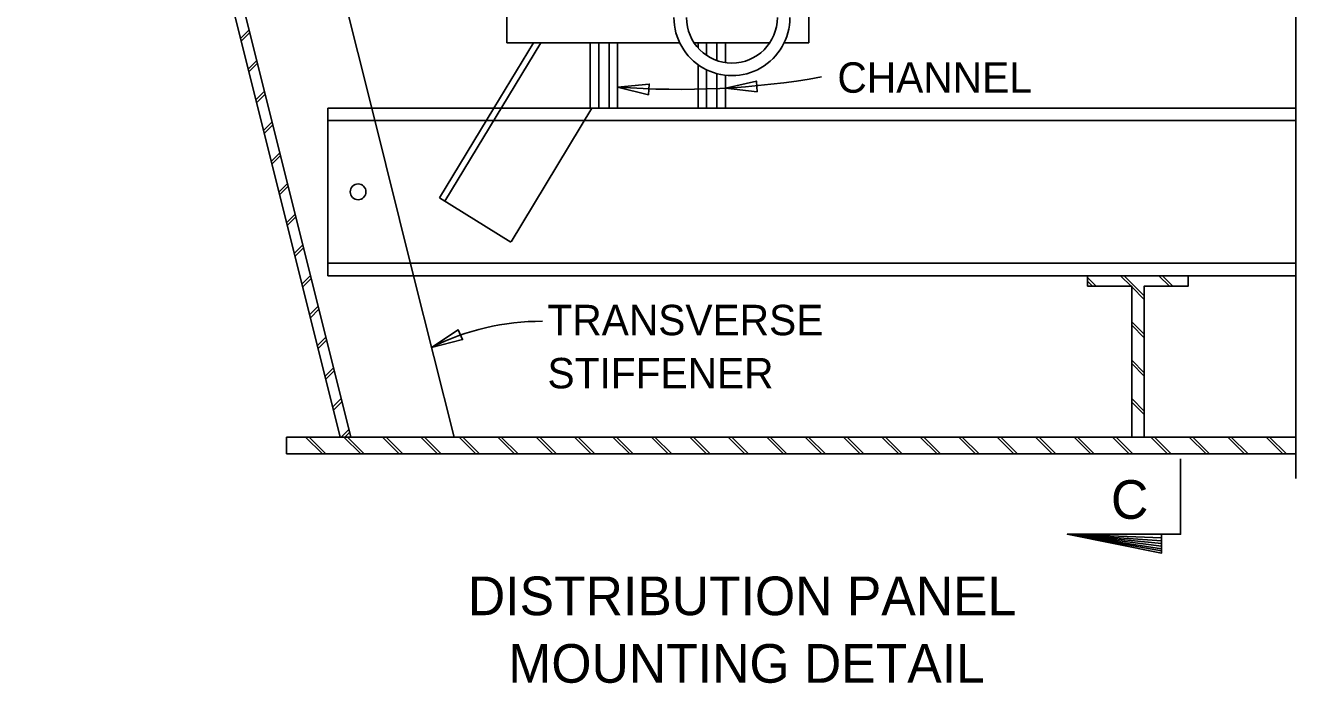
# Model space of a CAD drawing. Extents: x 927736.2 to 927809.6, y 636703.6 to 636757.7.
# Drawn here: x 927758.43 to 927774.19, y 636735.27 to 636743.33 of the extents above; entities that cross this region are included whole.
import ezdxf

# ---------------------------------------------------------------- set-up
doc = ezdxf.new("R2010")
doc.units = 0
for name, color, linetype in [('Default', 7, 'Continuous'), ('DimLines_dp', 7, 'Continuous'), ('Miscellaneous1', 7, 'Continuous'), ('Miscellaneous3', 7, 'Continuous')]:
    doc.layers.add(name, color=color, linetype=linetype)

msp = doc.modelspace()

# ---------------------------------------------------------------- linework, layer by layer
at = {"layer": 'DimLines_dp'}
for p, q in [((927772.357, 636737.056), (927771.201, 636737.099)), ((927771.201, 636737.099), (927772.357, 636737.019)), ((927772.357, 636736.985), (927771.201, 636737.099)), ((927771.201, 636737.099), (927772.357, 636736.951)), ((927772.357, 636736.92), (927771.201, 636737.099)), ((927771.201, 636737.099), (927772.357, 636736.895))]:
    msp.add_line(p, q, dxfattribs=at)
for points in [[(927774, 636737.782), (927774, 636747.055), (927773.809, 636747.055), (927774, 636747.139), (927774.191, 636747.222), (927774, 636747.222), (927774, 636756.677)], [(927772.589, 636738.024), (927772.589, 636737.099), (927771.201, 636737.099), (927772.357, 636736.867), (927772.357, 636737.099)]]:
    msp.add_lwpolyline(points, dxfattribs=at)
for points in [[(927765.688, 636742.581), (927766.067, 636742.487), (927766.077, 636742.617)], [(927767.01, 636742.568), (927767.398, 636742.524), (927767.391, 636742.654)], [(927763.409, 636739.389), (927763.788, 636739.484), (927763.736, 636739.603)]]:
    msp.add_lwpolyline(points, close=True, dxfattribs=at)
msp.add_arc((927766.454, 636752.53), 9.978, 265.6012, 280.0186, dxfattribs=at)
msp.add_ellipse((927764.747, 636736.471), major_axis=(-0.021, -3.238), ratio=0.953713, start_param=3.141601, end_param=3.59647, dxfattribs=at)
at = {"layer": 'Miscellaneous1'}
for p, q in [((927765.354, 636743.124), (927765.354, 636742.324)), ((927765.457, 636743.124), (927765.457, 636742.324)), ((927765.586, 636743.124), (927765.586, 636742.324)), ((927765.688, 636743.124), (927765.688, 636742.324)), ((927766.676, 636743.124), (927766.676, 636743.06)), ((927766.778, 636743.124), (927766.778, 636742.971)), ((927766.907, 636743.124), (927766.907, 636742.906)), ((927767.01, 636743.124), (927767.01, 636742.881)), ((927766.676, 636742.854), (927766.676, 636742.324)), ((927766.778, 636742.793), (927766.778, 636742.324)), ((927766.907, 636742.745), (927766.907, 636742.324)), ((927767.01, 636742.726), (927767.01, 636742.324))]:
    msp.add_line(p, q, dxfattribs=at)
for radius, start, end in [(0.711, 179.9955, 0.0001), (0.557, 180, 0)]:
    msp.add_arc((927767.09, 636743.432), radius, start, end, dxfattribs=at)
at = {"layer": 'Miscellaneous3'}
for p, q in [((927758.434, 636753.706), (927762.288, 636738.29)), ((927758.566, 636753.706), (927762.42, 636738.29)), ((927760.241, 636752.062), (927762.676, 636742.324)), ((927761.066, 636743.177), (927761.172, 636743.283)), ((927761.075, 636743.142), (927761.181, 636743.248)), ((927763.572, 636741.181), (927764.747, 636743.124)), ((927764.173, 636742.324), (927764.657, 636743.124)), ((927761.16, 636742.801), (927761.266, 636742.907)), ((927761.169, 636742.766), (927761.275, 636742.872)), ((927761.254, 636742.424), (927761.36, 636742.53)), ((927761.263, 636742.389), (927761.369, 636742.495)), ((927762.138, 636740.268), (927762.138, 636742.324)), ((927762.138, 636742.323), (927774, 636742.323)), ((927762.675, 636742.324), (927763.189, 636740.268)), ((927763.506, 636741.222), (927764.173, 636742.324)), ((927764.383, 636740.685), (927765.374, 636742.324)), ((927761.349, 636742.047), (927761.455, 636742.153)), ((927761.357, 636742.012), (927761.463, 636742.118)), ((927762.138, 636742.17), (927774, 636742.17)), ((927761.443, 636741.67), (927761.549, 636741.776)), ((927761.452, 636741.635), (927761.558, 636741.741)), ((927761.537, 636741.294), (927761.643, 636741.4)), ((927761.546, 636741.259), (927761.652, 636741.365)), ((927763.506, 636741.222), (927764.379, 636740.679)), ((927761.631, 636740.917), (927761.737, 636741.023)), ((927761.64, 636740.882), (927761.746, 636740.988)), ((927761.725, 636740.54), (927761.831, 636740.646)), ((927761.734, 636740.505), (927761.84, 636740.611)), ((927762.138, 636740.422), (927774, 636740.422)), ((927761.82, 636740.163), (927761.926, 636740.269)), ((927761.828, 636740.128), (927761.934, 636740.234)), ((927762.138, 636740.268), (927774, 636740.268)), ((927763.189, 636740.268), (927763.684, 636738.29)), ((927771.555, 636740.14), (927771.45, 636740.244)), ((927771.511, 636740.14), (927771.45, 636740.201)), ((927771.982, 636740.14), (927771.853, 636740.268)), ((927772.144, 636740.021), (927771.897, 636740.268)), ((927772.453, 636740.14), (927772.324, 636740.268)), ((927772.496, 636740.14), (927772.368, 636740.268)), ((927772.144, 636739.978), (927771.99, 636740.132)), ((927761.914, 636739.787), (927762.02, 636739.893)), ((927761.923, 636739.752), (927762.028, 636739.858)), ((927772.144, 636739.55), (927771.99, 636739.704)), ((927772.144, 636739.507), (927771.99, 636739.661)), ((927762.008, 636739.41), (927762.114, 636739.516)), ((927762.017, 636739.375), (927762.123, 636739.481)), ((927762.102, 636739.033), (927762.208, 636739.139)), ((927762.111, 636738.998), (927762.217, 636739.104)), ((927772.144, 636739.079), (927771.99, 636739.233)), ((927772.144, 636739.036), (927771.99, 636739.19)), ((927762.196, 636738.656), (927762.302, 636738.762)), ((927762.205, 636738.621), (927762.311, 636738.727)), ((927772.144, 636738.608), (927771.99, 636738.763)), ((927772.144, 636738.565), (927771.99, 636738.719)), ((927762.301, 636738.29), (927762.397, 636738.386)), ((927762.344, 636738.29), (927762.405, 636738.351)), ((927763.433, 636738.29), (927761.631, 636738.29)), ((927761.631, 636738.29), (927761.631, 636738.084)), ((927761.631, 636738.29), (927761.631, 636738.084)), ((927762.07, 636738.085), (927761.864, 636738.29)), ((927762.113, 636738.085), (927761.908, 636738.29)), ((927762.541, 636738.085), (927762.335, 636738.29)), ((927762.584, 636738.085), (927762.379, 636738.29)), ((927763.012, 636738.085), (927762.806, 636738.29)), ((927763.055, 636738.085), (927762.85, 636738.29)), ((927763.483, 636738.085), (927763.277, 636738.29)), ((927763.526, 636738.085), (927763.321, 636738.29)), ((927772.067, 636738.29), (927763.434, 636738.29)), ((927763.953, 636738.085), (927763.748, 636738.29)), ((927763.997, 636738.085), (927763.792, 636738.29)), ((927764.424, 636738.085), (927764.219, 636738.29)), ((927764.468, 636738.085), (927764.263, 636738.29)), ((927764.895, 636738.085), (927764.69, 636738.29)), ((927764.939, 636738.085), (927764.734, 636738.29)), ((927765.366, 636738.085), (927765.161, 636738.29)), ((927765.41, 636738.085), (927765.204, 636738.29)), ((927765.837, 636738.085), (927765.632, 636738.29)), ((927765.881, 636738.085), (927765.675, 636738.29)), ((927766.308, 636738.085), (927766.103, 636738.29)), ((927766.352, 636738.085), (927766.146, 636738.29)), ((927766.779, 636738.085), (927766.574, 636738.29)), ((927766.823, 636738.085), (927766.617, 636738.29)), ((927767.25, 636738.085), (927767.045, 636738.29)), ((927767.294, 636738.085), (927767.088, 636738.29)), ((927767.721, 636738.085), (927767.516, 636738.29)), ((927767.765, 636738.085), (927767.559, 636738.29)), ((927768.192, 636738.085), (927767.986, 636738.29)), ((927768.235, 636738.085), (927768.03, 636738.29)), ((927768.663, 636738.085), (927768.457, 636738.29)), ((927768.706, 636738.085), (927768.501, 636738.29)), ((927769.134, 636738.085), (927768.928, 636738.29)), ((927769.177, 636738.085), (927768.972, 636738.29)), ((927769.605, 636738.085), (927769.399, 636738.29)), ((927769.648, 636738.085), (927769.443, 636738.29)), ((927770.076, 636738.085), (927769.87, 636738.29)), ((927770.119, 636738.085), (927769.914, 636738.29)), ((927770.547, 636738.085), (927770.341, 636738.29)), ((927770.59, 636738.085), (927770.385, 636738.29)), ((927771.017, 636738.085), (927770.812, 636738.29)), ((927771.061, 636738.085), (927770.856, 636738.29)), ((927771.488, 636738.085), (927771.283, 636738.29)), ((927771.532, 636738.085), (927771.327, 636738.29)), ((927771.959, 636738.085), (927771.754, 636738.29)), ((927772.003, 636738.085), (927771.798, 636738.29)), ((927771.992, 636738.29), (927771.99, 636738.292)), ((927774, 636738.29), (927772.067, 636738.29)), ((927772.43, 636738.085), (927772.225, 636738.29)), ((927772.474, 636738.085), (927772.268, 636738.29)), ((927772.901, 636738.085), (927772.696, 636738.29)), ((927772.945, 636738.085), (927772.739, 636738.29)), ((927773.372, 636738.085), (927773.167, 636738.29)), ((927773.416, 636738.085), (927773.21, 636738.29)), ((927773.843, 636738.085), (927773.638, 636738.29)), ((927773.887, 636738.085), (927773.681, 636738.29)), ((927761.642, 636738.085), (927761.631, 636738.096)), ((927774, 636738.085), (927761.631, 636738.085))]:
    msp.add_line(p, q, dxfattribs=at)
for points in [[(927767.73, 636743.124), (927768.032, 636743.124), (927768.032, 636751.141), (927765.842, 636751.141)], [(927764.332, 636748.324), (927764.332, 636743.124), (927766.449, 636743.124)], [(927766.626, 636743.124), (927767.553, 636743.124)]]:
    msp.add_lwpolyline(points, dxfattribs=at)
msp.add_lwpolyline([(927771.99, 636738.29), (927771.99, 636740.14), (927771.45, 636740.14), (927771.45, 636740.268), (927772.683, 636740.268), (927772.683, 636740.14), (927772.144, 636740.14), (927772.144, 636738.29)], close=True, dxfattribs=at)
msp.add_circle((927762.508, 636741.296), 0.0964, dxfattribs=at)

# ---------------------------------------------------------------- texts
at = {"layer": 'Default'}
for s, p in [('DISTRIBUTION PANEL', (927763.854, 636736.106)), ('MOUNTING DETAIL', (927764.349, 636735.278))]:
    msp.add_text(s, height=0.4736, dxfattribs=at).set_placement(p)
at = {"layer": 'DimLines_dp'}
for s, height, p in [('CHANNEL', 0.373, (927768.383, 636742.511)), ('TRANSVERSE', 0.373, (927764.829, 636739.538)), ('STIFFENER', 0.373, (927764.829, 636738.887)), ('C', 0.474, (927771.736, 636737.287))]:
    msp.add_text(s, height=height, dxfattribs=at).set_placement(p)

doc.saveas('drawing.dxf')
